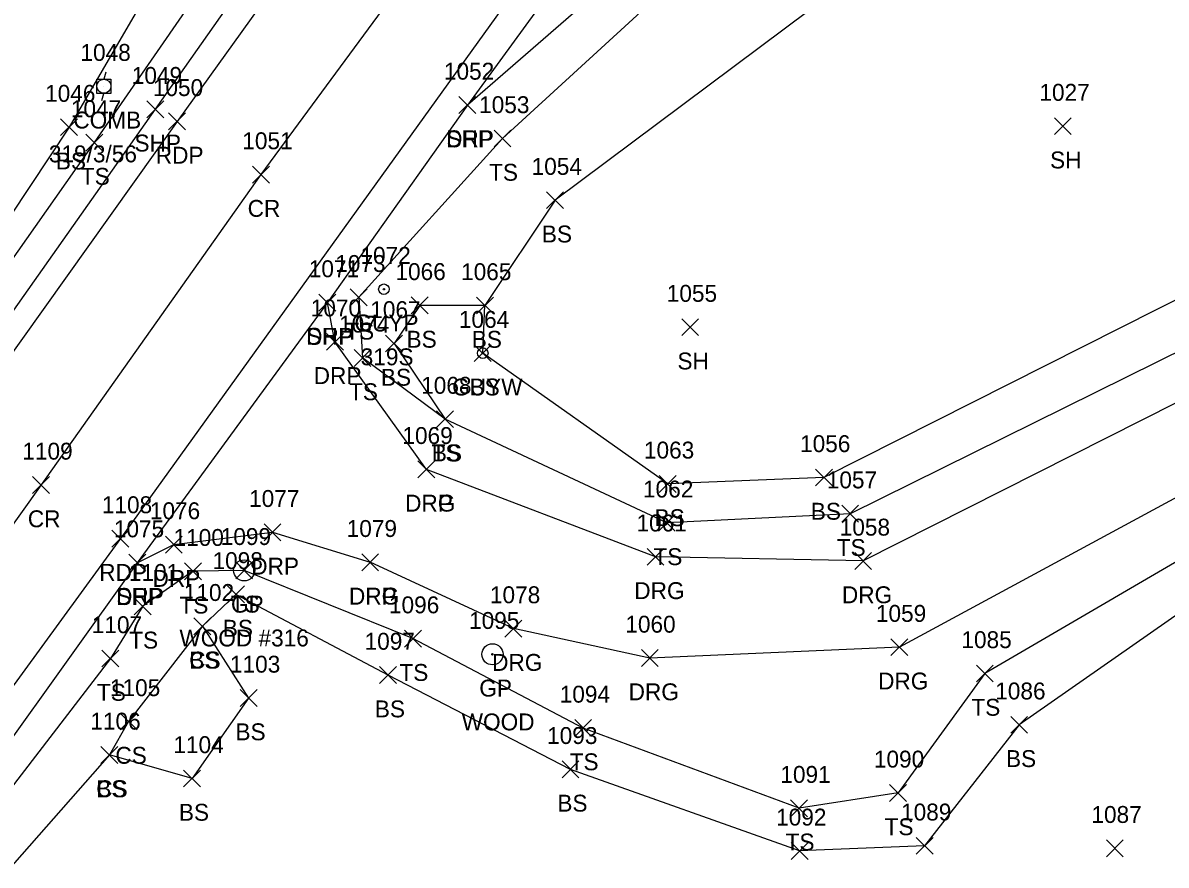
# Model space of a CAD drawing. Extents: x 1520648 to 1523413, y 732854 to 735518.
# Drawn here: x 1522789.8 to 1522925, y 734648.2 to 734747.8 of the extents above; entities that cross this region are included whole.
import ezdxf

# ---------------------------------------------------------------- set-up
doc = ezdxf.new("R2010")
doc.units = 0
for name, color, linetype in [('L_A', 7, 'Continuous'), ('L_I', 7, 'Continuous'), ('L_TIC', 7, 'Continuous'), ('LELB', 7, 'Continuous'), ('P_A', 7, 'Continuous'), ('P_I', 7, 'Continuous'), ('P_TIC', 7, 'Continuous'), ('PET', 7, 'Continuous'), ('PRC', 7, 'Continuous'), ('PSP', 7, 'Continuous'), ('R_A', 7, 'Continuous'), ('R_C', 7, 'Continuous'), ('R_I', 7, 'Continuous'), ('R_TIC', 7, 'Continuous'), ('RDG', 7, 'Continuous'), ('RDP', 7, 'Continuous'), ('RGP', 7, 'Continuous'), ('U_A', 7, 'Continuous'), ('U_C', 7, 'Continuous'), ('U_I', 7, 'Continuous'), ('UP', 7, 'Continuous'), ('UPGW', 7, 'Continuous')]:
    doc.layers.add(name, color=color, linetype=linetype)

msp = doc.modelspace()

# ---------------------------------------------------------------- linework, layer by layer
at = {"layer": 'L_TIC'}
for points in [[(1522794.28, 734734.47), (1522796.28, 734736.47)], [(1522796.28, 734734.47), (1522794.28, 734736.47)], [(1522911.79, 734734.59), (1522913.79, 734736.59)], [(1522913.79, 734734.59), (1522911.79, 734736.59)], [(1522845.54, 734733.13), (1522847.54, 734735.13)], [(1522847.54, 734733.13), (1522845.54, 734735.13)], [(1522797.27, 734732.65), (1522799.27, 734734.65)], [(1522799.27, 734732.65), (1522797.27, 734734.65)], [(1522851.75, 734725.83), (1522853.75, 734727.83)], [(1522853.75, 734725.83), (1522851.75, 734727.83)], [(1522828.53, 734714.34), (1522830.53, 734716.34)], [(1522830.53, 734714.34), (1522828.53, 734716.34)], [(1522835.75, 734713.38), (1522837.75, 734715.38)], [(1522837.75, 734713.38), (1522835.75, 734715.38)], [(1522843.46, 734713.37), (1522845.46, 734715.37)], [(1522845.46, 734713.37), (1522843.46, 734715.37)], [(1522843.46, 734713.37), (1522845.46, 734715.37)], [(1522845.46, 734713.37), (1522843.46, 734715.37)], [(1522867.73, 734710.81), (1522869.73, 734712.81)], [(1522869.73, 734710.81), (1522867.73, 734712.81)], [(1522832.72, 734708.88), (1522834.72, 734710.88)], [(1522834.72, 734708.88), (1522832.72, 734710.88)], [(1522843.2, 734707.73), (1522845.2, 734709.73)], [(1522845.2, 734707.73), (1522843.2, 734709.73)], [(1522828.98, 734707.17), (1522830.98, 734709.17)], [(1522830.98, 734707.17), (1522828.98, 734709.17)], [(1522828.98, 734707.17), (1522830.98, 734709.17)], [(1522830.98, 734707.17), (1522828.98, 734709.17)], [(1522838.74, 734699.93), (1522840.74, 734701.93)], [(1522840.74, 734699.93), (1522838.74, 734701.93)], [(1522838.74, 734699.93), (1522840.74, 734701.93)], [(1522840.74, 734699.93), (1522838.74, 734701.93)], [(1522883.55, 734693.03), (1522885.55, 734695.03)], [(1522885.55, 734693.03), (1522883.55, 734695.03)], [(1522865.08, 734692.27), (1522867.08, 734694.27)], [(1522867.08, 734692.27), (1522865.08, 734694.27)], [(1522886.65, 734688.74), (1522888.65, 734690.74)], [(1522888.65, 734688.74), (1522886.65, 734690.74)], [(1522864.97, 734687.66), (1522866.97, 734689.66)], [(1522866.97, 734687.66), (1522864.97, 734689.66)], [(1522808.93, 734681.93), (1522810.93, 734683.93)], [(1522810.93, 734681.93), (1522808.93, 734683.93)], [(1522814.99, 734682.04), (1522816.99, 734684.04)], [(1522816.99, 734682.04), (1522814.99, 734684.04)], [(1522814.02, 734679.19), (1522816.02, 734681.19)], [(1522816.02, 734679.19), (1522814.02, 734681.19)], [(1522802.99, 734677.79), (1522804.99, 734679.79)], [(1522804.99, 734677.79), (1522802.99, 734679.79)], [(1522810.05, 734675.42), (1522812.05, 734677.42)], [(1522812.05, 734675.42), (1522810.05, 734677.42)], [(1522810.05, 734675.42), (1522812.05, 734677.42)], [(1522812.05, 734675.42), (1522810.05, 734677.42)], [(1522834.94, 734673.96), (1522836.94, 734675.96)], [(1522836.94, 734673.96), (1522834.94, 734675.96)], [(1522799.17, 734671.61), (1522801.17, 734673.61)], [(1522801.17, 734671.61), (1522799.17, 734673.61)], [(1522832, 734669.65), (1522834, 734671.65)], [(1522834, 734669.65), (1522832, 734671.65)], [(1522902.57, 734669.84), (1522904.57, 734671.84)], [(1522904.57, 734669.84), (1522902.57, 734671.84)], [(1522815.52, 734666.94), (1522817.52, 734668.94)], [(1522817.52, 734666.94), (1522815.52, 734668.94)], [(1522801.32, 734664.16), (1522803.32, 734666.16)], [(1522803.32, 734664.16), (1522801.32, 734666.16)], [(1522855.07, 734663.39), (1522857.07, 734665.39)], [(1522857.07, 734663.39), (1522855.07, 734665.39)], [(1522906.63, 734663.77), (1522908.63, 734665.77)], [(1522908.63, 734663.77), (1522906.63, 734665.77)], [(1522799.06, 734660.2), (1522801.06, 734662.2)], [(1522801.06, 734660.2), (1522799.06, 734662.2)], [(1522799.06, 734660.2), (1522801.06, 734662.2)], [(1522801.06, 734660.2), (1522799.06, 734662.2)], [(1522808.83, 734657.42), (1522810.83, 734659.42)], [(1522810.83, 734657.42), (1522808.83, 734659.42)], [(1522853.58, 734658.5), (1522855.58, 734660.5)], [(1522855.58, 734658.5), (1522853.58, 734660.5)], [(1522892.31, 734655.71), (1522894.31, 734657.71)], [(1522894.31, 734655.71), (1522892.31, 734657.71)], [(1522880.6, 734653.9), (1522882.6, 734655.9)], [(1522882.6, 734653.9), (1522880.6, 734655.9)], [(1522895.44, 734649.45), (1522897.44, 734651.45)], [(1522897.44, 734649.45), (1522895.44, 734651.45)], [(1522917.94, 734649.16), (1522919.94, 734651.16)], [(1522919.94, 734649.16), (1522917.94, 734651.16)], [(1522880.66, 734648.85), (1522882.66, 734650.85)], [(1522882.66, 734648.85), (1522880.66, 734650.85)]]:
    msp.add_lwpolyline(points, dxfattribs=at)
at = {"layer": 'LELB'}
for points in [[(1522855.1, 734830.16), (1522826.24, 734788.65), (1522795.28, 734735.47), (1522774.39, 734704.01), (1522748.32, 734671.46), (1522720.6, 734629.79), (1522692.36, 734589.33), (1522661.51, 734546.14), (1522629.11, 734507.98), (1522627.63, 734508.21), (1522631.88, 734521.21)], [(1522861.38, 734825.29), (1522833.52, 734784.68), (1522798.27, 734733.65), (1522776.55, 734702.76), (1522751.5, 734669.07), (1522723.71, 734627.99), (1522694.34, 734587.49), (1522663.89, 734544.83), (1522637.49, 734508.77), (1522629.88, 734505.43), (1522625.31, 734507.86), (1522622.08, 734509.21)], [(1522910.81, 734790.08), (1522907.66, 734785.39), (1522898.01, 734784.03), (1522876.43, 734761.54), (1522846.54, 734734.13), (1522829.53, 734715.34), (1522829.98, 734708.17)], [(1522921.1, 734785.69), (1522889.01, 734753.95), (1522852.75, 734726.83), (1522844.46, 734714.37), (1522836.75, 734714.38), (1522833.72, 734709.88), (1522839.74, 734700.93)], [(1522974.07, 734746.69), (1522937.1, 734720.55), (1522884.55, 734694.03), (1522866.08, 734693.27), (1522844.2, 734708.73), (1522844.46, 734714.37)], [(1522979.6, 734741.14), (1522942.08, 734716.67), (1522887.65, 734689.74), (1522865.97, 734688.66), (1522839.74, 734700.93), (1522829.98, 734708.17)], [(1522964.59, 734711.8), (1522934.04, 734688.62), (1522903.57, 734670.84), (1522893.31, 734656.71), (1522881.6, 734654.9), (1522856.07, 734664.39), (1522835.94, 734674.96), (1522815.99, 734683.04), (1522809.93, 734682.93), (1522803.99, 734678.79), (1522800.17, 734672.61), (1522781.12, 734647.81), (1522752.35, 734609.03), (1522722.77, 734569.04), (1522693.92, 734527.21), (1522653.61, 734471.8)], [(1522966.98, 734707.81), (1522936.6, 734685.01), (1522907.63, 734664.77), (1522896.44, 734650.45), (1522881.66, 734649.85), (1522854.58, 734659.5), (1522833, 734670.65), (1522815.02, 734680.19), (1522811.05, 734676.42), (1522816.52, 734667.94), (1522809.83, 734658.42), (1522800.06, 734661.2), (1522785.93, 734645.15), (1522763.72, 734601.03), (1522733.15, 734561.61), (1522704.24, 734521.86), (1522660.18, 734466.65)], [(1522811.05, 734676.42), (1522802.32, 734665.16), (1522800.06, 734661.2)]]:
    msp.add_lwpolyline(points, dxfattribs=at)
at = {"layer": 'P_TIC'}
for points in [[(1522841.38, 734737.09), (1522843.38, 734739.09)], [(1522843.38, 734737.09), (1522841.38, 734739.09)], [(1522804.48, 734736.59), (1522806.48, 734738.59)], [(1522806.48, 734736.59), (1522804.48, 734738.59)], [(1522807.05, 734735.15), (1522809.05, 734737.15)], [(1522809.05, 734735.15), (1522807.05, 734737.15)], [(1522816.97, 734728.86), (1522818.97, 734730.86)], [(1522818.97, 734728.86), (1522816.97, 734730.86)], [(1522824.83, 734713.72), (1522826.83, 734715.72)], [(1522826.83, 734713.72), (1522824.83, 734715.72)], [(1522790.97, 734692.14), (1522792.97, 734694.14)], [(1522792.97, 734692.14), (1522790.97, 734694.14)], [(1522800.36, 734685.8), (1522802.36, 734687.8)], [(1522802.36, 734685.8), (1522800.36, 734687.8)], [(1522802.35, 734682.95), (1522804.35, 734684.95)], [(1522804.35, 734682.95), (1522802.35, 734684.95)]]:
    msp.add_lwpolyline(points, dxfattribs=at)
at = {"layer": 'PET'}
for points in [[(1522868.59, 734820.36), (1522840.66, 734781.56), (1522808.05, 734736.15), (1522781.8, 734699.35), (1522756.93, 734664.88), (1522728.19, 734624.99), (1522698.77, 734583.51), (1522668.99, 734541.94), (1522630.29, 734488.99), (1522594.44, 734439.3), (1522567.25, 734402.07), (1522538.71, 734362.22), (1522514.31, 734328.64), (1522482.43, 734284.06), (1522464.74, 734260.16), (1522432.63, 734216.53), (1522409.89, 734185.46), (1522384.8, 734151.86)], [(1522887.76, 734807.39), (1522860.85, 734769.52), (1522801.36, 734686.8), (1522776.05, 734652.1), (1522748.04, 734612.12), (1522718.66, 734571.41), (1522688.63, 734530.01), (1522649.15, 734475.23), (1522613.31, 734425.7), (1522584.29, 734385.79), (1522558.85, 734350.63), (1522533.2, 734315.44), (1522501.29, 734271.61), (1522483.1, 734246.38), (1522451.17, 734203.52), (1522426.47, 734169.3), (1522405.75, 734141.77), (1522378.63, 734104.64)]]:
    msp.add_lwpolyline(points, dxfattribs=at)
at = {"layer": 'PRC'}
msp.add_lwpolyline([(1522878.51, 734813.79), (1522851.06, 734774.87), (1522817.97, 734729.86), (1522791.97, 734693.14), (1522766.66, 734657.61), (1522738.9, 734618.17), (1522708.24, 734576.9), (1522678.84, 734535.68), (1522640.14, 734482.21), (1522604.52, 734432.45), (1522576.44, 734394.44), (1522548.3, 734356.14), (1522523.72, 734322.36), (1522491.79, 734277.99), (1522474.03, 734253.33), (1522442.17, 734210.31), (1522417.88, 734177.66), (1522396.73, 734148.57), (1522369.92, 734111.45)], dxfattribs=at)
at = {"layer": 'PSP'}
for points in [[(1522864.28, 734823.23), (1522837.44, 734783.06), (1522805.48, 734737.59), (1522779.45, 734700.71), (1522754.96, 734666.26), (1522726.27, 734626.48), (1522696.55, 734585.36), (1522666.29, 734543.52), (1522637.15, 734503.6), (1522619.94, 734478.45), (1522592.3, 734440.3), (1522565.28, 734403.71), (1522536.3, 734363.73), (1522513.91, 734332.75), (1522468.75, 734270.57), (1522462.45, 734261.84), (1522430.53, 734218.51), (1522407.44, 734186.96), (1522382.7, 734153.4)], [(1522891.61, 734804.38), (1522863.83, 734767.51), (1522842.38, 734738.09), (1522825.83, 734714.72), (1522803.35, 734683.95), (1522778.9, 734649.79), (1522750.84, 734610.4), (1522721.18, 734569.96), (1522691.62, 734528.08), (1522651.91, 734473.19), (1522616.71, 734423.72), (1522586.83, 734383.52), (1522561.92, 734348.87), (1522535.83, 734313.09), (1522504.54, 734270.39), (1522485.78, 734244.5), (1522453.37, 734201.19), (1522428.68, 734167.53), (1522408.2, 734139.28), (1522381.04, 734102.47)]]:
    msp.add_lwpolyline(points, dxfattribs=at)
at = {"layer": 'R_TIC'}
for points in [[(1522841.38, 734737.09), (1522843.38, 734739.09)], [(1522843.38, 734737.09), (1522841.38, 734739.09)], [(1522824.83, 734713.72), (1522826.83, 734715.72)], [(1522826.83, 734713.72), (1522824.83, 734715.72)], [(1522825.72, 734709.08), (1522827.72, 734711.08)], [(1522827.72, 734709.08), (1522825.72, 734711.08)], [(1522836.53, 734693.99), (1522838.53, 734695.99)], [(1522838.53, 734693.99), (1522836.53, 734695.99)], [(1522836.53, 734693.99), (1522838.53, 734695.99)], [(1522838.53, 734693.99), (1522836.53, 734695.99)], [(1522818.34, 734686.54), (1522820.34, 734688.54)], [(1522820.34, 734686.54), (1522818.34, 734688.54)], [(1522806.67, 734685.09), (1522808.67, 734687.09)], [(1522808.67, 734685.09), (1522806.67, 734687.09)], [(1522829.89, 734682.99), (1522831.89, 734684.99)], [(1522831.89, 734682.99), (1522829.89, 734684.99)], [(1522829.89, 734682.99), (1522831.89, 734684.99)], [(1522831.89, 734682.99), (1522829.89, 734684.99)], [(1522863.63, 734683.64), (1522865.63, 734685.64)], [(1522865.63, 734683.64), (1522863.63, 734685.64)], [(1522888.18, 734683.15), (1522890.18, 734685.15)], [(1522890.18, 734683.15), (1522888.18, 734685.15)], [(1522802.35, 734682.95), (1522804.35, 734684.95)], [(1522804.35, 734682.95), (1522802.35, 734684.95)], [(1522846.82, 734675.15), (1522848.82, 734677.15)], [(1522848.82, 734675.15), (1522846.82, 734677.15)], [(1522892.47, 734672.95), (1522894.47, 734674.95)], [(1522894.47, 734672.95), (1522892.47, 734674.95)], [(1522862.96, 734671.67), (1522864.96, 734673.67)], [(1522864.96, 734671.67), (1522862.96, 734673.67)]]:
    msp.add_lwpolyline(points, dxfattribs=at)
at = {"layer": 'RDG'}
for points in [[(1522982.91, 734738.83), (1522946.8, 734713.25), (1522889.18, 734684.15), (1522864.63, 734684.64), (1522837.53, 734694.99)], [(1522989.86, 734733.25), (1522955.36, 734707.45), (1522893.47, 734673.95), (1522863.96, 734672.67), (1522847.82, 734676.15), (1522830.89, 734683.99)]]:
    msp.add_lwpolyline(points, dxfattribs=at)
at = {"layer": 'RDP'}
for points in [[(1522901.57, 734796.24), (1522872.22, 734764.01), (1522842.38, 734738.09)], [(1522837.53, 734694.99), (1522826.72, 734710.08), (1522825.83, 734714.72)], [(1522803.35, 734683.95), (1522807.67, 734686.09), (1522819.34, 734687.54), (1522830.89, 734683.99)]]:
    msp.add_lwpolyline(points, dxfattribs=at)
at = {"layer": 'RGP'}
for p, q in [((1522815.99, 734683.04), (1522815.99, 734683.04)), ((1522845.35, 734673.11), (1522845.35, 734673.11))]:
    msp.add_line(p, q, dxfattribs=at)
for centre, radius in [((1522815.99, 734683.04), 1.25), ((1522815.99, 734683.04), 0.0833), ((1522845.35, 734673.11), 1.25), ((1522845.35, 734673.11), 0.0833)]:
    msp.add_circle(centre, radius, dxfattribs=at)
at = {"layer": 'UP'}
for p, q in [((1522799.65, 734741.97), (1522799.4, 734741.14)), ((1522798.57, 734739.47), (1522798.57, 734741.14)), ((1522798.57, 734741.14), (1522800.23, 734741.14)), ((1522800.23, 734741.14), (1522800.23, 734739.47)), ((1522800.23, 734739.47), (1522798.57, 734739.47)), ((1522799.15, 734738.64), (1522799.4, 734739.47)), ((1522799.4, 734740.31), (1522799.4, 734740.31))]:
    msp.add_line(p, q, dxfattribs=at)
msp.add_circle((1522799.4, 734740.31), 0.833, dxfattribs=at)
at = {"layer": 'UPGW'}
for centre, radius in [((1522832.51, 734716.3), 0.625), ((1522832.51, 734716.3), 0.0833), ((1522844.2, 734708.73), 0.625), ((1522844.2, 734708.73), 0.0833)]:
    msp.add_circle(centre, radius, dxfattribs=at)

# ---------------------------------------------------------------- texts
at = {"layer": 'L_A'}
for s, p in [('BS', (1522793.72, 734730.47)), ('SH', (1522911.28, 734730.59)), ('TS', (1522844.95, 734729.13)), ('TS', (1522796.68, 734728.65)), ('BS', (1522851.19, 734721.83)), ('TS', (1522827.94, 734710.34)), ('BS', (1522835.19, 734709.38)), ('BS', (1522842.9, 734709.37)), ('BS', (1522842.9, 734709.37)), ('SH', (1522867.22, 734706.81)), ('BS', (1522832.16, 734704.88)), ('BS', (1522842.64, 734703.73)), ('TS', (1522828.39, 734703.17)), ('TS', (1522828.39, 734703.17)), ('TS', (1522838.15, 734695.93)), ('BS', (1522838.18, 734695.93)), ('BS', (1522882.99, 734689.03)), ('BS', (1522864.52, 734688.27)), ('TS', (1522886.06, 734684.74)), ('TS', (1522864.38, 734683.66)), ('TS', (1522808.34, 734677.93)), ('TS', (1522814.4, 734678.04)), ('BS', (1522813.46, 734675.19)), ('TS', (1522802.4, 734673.79)), ('CS', (1522809.49, 734671.42)), ('BS', (1522809.49, 734671.42)), ('TS', (1522834.35, 734669.96)), ('TS', (1522798.58, 734667.61)), ('BS', (1522831.44, 734665.65)), ('TS', (1522901.98, 734665.84)), ('BS', (1522814.96, 734662.94)), ('CS', (1522800.76, 734660.16)), ('TS', (1522854.48, 734659.39)), ('BS', (1522906.07, 734659.77)), ('CS', (1522798.5, 734656.2)), ('BS', (1522798.5, 734656.2)), ('BS', (1522808.27, 734653.42)), ('BS', (1522853.02, 734654.5)), ('TS', (1522891.72, 734651.71)), ('TS', (1522880.01, 734649.9))]:
    msp.add_text(s, height=2, dxfattribs=at).set_placement(p)
at = {"layer": 'L_I'}
for s, p in [('1046', (1522792.45, 734738.47)), ('1027', (1522910.02, 734738.59)), ('1053', (1522843.77, 734737.13)), ('1047', (1522795.5, 734736.65)), ('1054', (1522849.98, 734729.83)), ('1073', (1522826.76, 734718.34)), ('1066', (1522833.88, 734717.38)), ('1065', (1522841.64, 734717.37)), ('1065', (1522841.64, 734717.37)), ('1055', (1522865.96, 734714.81)), ('1067', (1522830.9, 734712.88)), ('1064', (1522841.38, 734711.73)), ('1074', (1522827.21, 734711.17)), ('1074', (1522827.21, 734711.17)), ('1068', (1522836.92, 734703.93)), ('1068', (1522836.92, 734703.93)), ('1056', (1522881.72, 734697.03)), ('1063', (1522863.26, 734696.27)), ('1057', (1522884.88, 734692.74)), ('1062', (1522863.15, 734691.66)), ('1100', (1522807.64, 734685.93)), ('1099', (1522813.22, 734686.04)), ('1098', (1522812.25, 734683.19)), ('1101', (1522802.36, 734681.79)), ('1102', (1522808.85, 734679.42)), ('1102', (1522808.85, 734679.42)), ('1096', (1522833.11, 734677.96)), ('1107', (1522797.97, 734675.61)), ('1097', (1522830.23, 734673.65)), ('1085', (1522900.8, 734673.84)), ('1103', (1522814.31, 734670.94)), ('1105', (1522800.12, 734668.16)), ('1094', (1522853.3, 734667.39)), ('1086', (1522904.8, 734667.77)), ('1106', (1522797.8, 734664.2)), ('1106', (1522797.8, 734664.2)), ('1104', (1522807.62, 734661.42)), ('1093', (1522851.81, 734662.5)), ('1090', (1522890.45, 734659.71)), ('1091', (1522879.39, 734657.9)), ('1089', (1522893.66, 734653.45)), ('1092', (1522878.89, 734652.85)), ('1087', (1522916.17, 734653.16))]:
    msp.add_text(s, height=2, dxfattribs=at).set_placement(p)
at = {"layer": 'P_A'}
for s, p in [('SHP', (1522839.92, 734733.09)), ('SHP', (1522803.02, 734732.59)), ('RDP', (1522805.54, 734731.15)), ('CR', (1522816.4, 734724.86)), ('SHP', (1522823.37, 734709.72)), ('CR', (1522790.41, 734688.14)), ('RDP', (1522798.85, 734681.8)), ('SHP', (1522800.89, 734678.95))]:
    msp.add_text(s, height=2, dxfattribs=at).set_placement(p)
at = {"layer": 'P_I'}
for s, p in [('1052', (1522839.61, 734741.09)), ('1049', (1522802.7, 734740.59)), ('1050', (1522805.19, 734739.15)), ('1051', (1522815.77, 734732.86)), ('1071', (1522823.63, 734717.72)), ('1109', (1522789.76, 734696.14)), ('1108', (1522799.16, 734689.8)), ('1075', (1522800.58, 734686.95))]:
    msp.add_text(s, height=2, dxfattribs=at).set_placement(p)
at = {"layer": 'R_A'}
for s, p in [('DRP', (1522839.87, 734733.09)), ('DRP', (1522823.32, 734709.72)), ('DRP', (1522824.21, 734705.08)), ('DRG', (1522835.02, 734689.99)), ('DRP', (1522835.02, 734689.99)), ('DRP', (1522816.83, 734682.54)), ('DRP', (1522805.16, 734681.09)), ('DRP', (1522800.84, 734678.95)), ('DRG', (1522828.38, 734678.99)), ('DRP', (1522828.38, 734678.99)), ('DRG', (1522862.12, 734679.64)), ('DRG', (1522886.67, 734679.15)), ('GP', (1522814.43, 734678.04)), ('DRG', (1522845.31, 734671.15)), ('GP', (1522843.79, 734668.11)), ('DRG', (1522890.95, 734668.95)), ('DRG', (1522861.45, 734667.67))]:
    msp.add_text(s, height=2, dxfattribs=at).set_placement(p)
at = {"layer": 'R_C'}
for s, p in [('WOOD #316', (1522808.33, 734674.04)), ('WOOD', (1522841.71, 734664.11))]:
    msp.add_text(s, height=2, dxfattribs=at).set_placement(p)
at = {"layer": 'R_I'}
for s, p in [('1052', (1522839.61, 734741.09)), ('1071', (1522823.63, 734717.72)), ('1070', (1522823.86, 734713.08)), ('1069', (1522834.7, 734697.99)), ('1069', (1522834.7, 734697.99)), ('1077', (1522816.57, 734690.54)), ('1076', (1522804.84, 734689.09)), ('1079', (1522828.11, 734686.99)), ('1079', (1522828.11, 734686.99)), ('1061', (1522862.38, 734687.64)), ('1058', (1522886.41, 734687.15)), ('1075', (1522800.58, 734686.95)), ('1099', (1522813.22, 734686.04)), ('1078', (1522845.05, 734679.15)), ('1059', (1522890.69, 734676.95)), ('1095', (1522842.58, 734676.11)), ('1060', (1522861.06, 734675.67))]:
    msp.add_text(s, height=2, dxfattribs=at).set_placement(p)
at = {"layer": 'U_A'}
for s, p in [('COMB', (1522795.79, 734735.31)), ('GUYP', (1522829.03, 734711.3)), ('GUYW', (1522840.59, 734703.73))]:
    msp.add_text(s, height=2, dxfattribs=at).set_placement(p)
at = {"layer": 'U_C'}
for s, p in [('319/3/56', (1522792.9, 734731.31)), ('319S', (1522829.77, 734707.3))]:
    msp.add_text(s, height=2, dxfattribs=at).set_placement(p)
at = {"layer": 'U_I'}
for s, p in [('1048', (1522796.63, 734743.31)), ('1072', (1522829.74, 734719.3)), ('1064', (1522841.38, 734711.73))]:
    msp.add_text(s, height=2, dxfattribs=at).set_placement(p)

doc.saveas('drawing.dxf')
